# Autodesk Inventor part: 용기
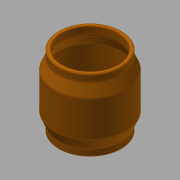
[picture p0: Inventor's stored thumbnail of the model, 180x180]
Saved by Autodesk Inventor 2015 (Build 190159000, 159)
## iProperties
Created: 2018-01
Part Number: 용기
Material: ABS 플라스틱
Document SubType Name: Modeling
Designer: mduedu
Density: 1 g/cm^3
Appearance: 주황색
Author: mduedu
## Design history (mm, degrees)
sketch "스케치1"
  geometry: L1 (0, 0)-(-35, 0); L2 (-35, 0)-(-35, 8); L3 (-35, 8)-(-40, 20); L4 (-40, 20)-(-40, 60); L5 (-40, 60)-(-35, 72); L6 (-35, 72)-(-35, 80); L7 (-35, 80)-(0, 80); L8 (0, 80)-(0, 0)
  constraints: 16 end point, 3 collinear, 3 parallel, 1 horizontal, 1 perpendicular
  dimensions: "d0" = 8 distance of L1.end L2.end; "d2" = 70 diameter of L2 L8; "d3" = 20 distance from line of L3.end L1; "d4" = 60 distance from line of L4.end L1; "d5" = 20 distance from line of L4.end L7; "d6" = 80 diameter of L4 L8
revolve "회전1" sketch "스케치1" stored, may be unused: angle "d7" = 90 deg
fillet "모깎기1" dims "d8" = 3
feature "쉘1" dims "d9" = 4
fillet "모깎기2" dims "d10" = 1
chamfer "모따기1" distance "d11" = 0.5; stored, may be unused: second distance "d12" = 2, angle "d13" = 45 deg
node "솔리드1"
